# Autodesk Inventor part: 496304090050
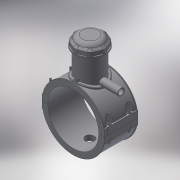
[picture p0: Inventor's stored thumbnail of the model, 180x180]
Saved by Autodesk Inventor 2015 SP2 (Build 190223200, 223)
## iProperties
Created: 2017-07
Part Number: 496304090050
Material: Generic
Description: PLASSON TAPPING SADDLE 90x50
Document SubType Name: Modeling
Designer: KIM
Mass: 716.955 g
Surface Area: 1792.48 cm^2
Volume: 716.955 cm^3
Density: 1 g/cm^3
Appearance: Default
Author: KIM
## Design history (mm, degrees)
derived "496304.ipt"
feature "Solid1::496304.ipt"
feature "Solid2::496304.ipt"
feature "Solid4::496304.ipt"
feature "Solid5::496304.ipt"
tag "TaggingFeature1"
body "Solid1"
body "Solid2"
other parameters: "d2" = 126, "d3" = 22.5, "d4" = 118, "d5" = 0, "d6" = 0.1, "d8" = 0, "d19" = 6, "d20" = 6, "d21" = 70.8, "d23" = 0, "d24" = 35.4, "d26" = 0, "d29" = 3, "d31" = 6, "d32" = 0, "d33" = 0, "d34" = 0.6, "d40" = 58.032, "d41" = 63, "d43" = 0, "d45" = 0, "d47" = 126.6, "d70" = 15, "d72" = 0, "d73" = 6, "d75" = 5, "d76" = 0, "d77" = 4.5, "d78" = 75, "d79" = 15, "d80" = 47.2, "d82" = 5 deg, "d84" = 4, "d85" = 14, "d86" = 0, "d87" = 3, "d88" = 0, "d89" = 1, "d90" = 1, "d91" = 94.4, "d92" = 0, "d93" = 0.5, "d94" = 47.36842, "d96" = 113.832, "d97" = 2.36, "d98" = 0, "d102" = 0.9, "d120" = 140 deg, "d121" = 24.228, "d122" = 20 deg, "d123" = 223.2, "d124" = 66.96, "d126" = 0, "d143" = 92.7, "d145" = 16.61538, "d149" = 1.35, "d150" = 18.27692, "d153" = 118, "d154" = 0, "d156" = 55.8, "d157" = 160 deg, "d159" = 4.32, "d161" = 1.35, "d162" = 70.8, "d163" = 0, "d164" = 45, "d167" = 9, "d168" = 54.43902, "d170" = 3.375, "d172" = 0, "d173" = 1, "d175" = 45, "d176" = 20 deg, "d177" = 6.3, "d178" = 21.6, "d180" = 0, "d183" = 8.64, "d184" = 5.04, "d185" = 38.35, "d186" = 38.35, "d187" = 55.8, "d188" = 6.48, "d189" = 6.3, "d190" = 0, "d191" = 83.7, "d193" = 6.3, "d194" = 4.13, "d195" = 90 deg, "d197" = 0, "d199" = 0, "d200" = 10.8, "d202" = 0, "d203" = 177, "d204" = 59.85, "d205" = 44.1, "d206" = 53.55, "d207" = 132.75, "d208" = 138.06, "d209" = 164.61, "d210" = 54.18, "d211" = 63, "d212" = 50.4, "d213" = 35.1, "d216" = 0, "d217" = 9, "d218" = 9, "d219" = 1.8, "d224" = 0, "d230" = 5.4, "d233" = 6, "d236" = 63, "d237" = 35.4, "d238" = 6.02433, "d240" = 35.4, "d241" = 35.4, "d242" = 35.4, "d243" = 6, "d244" = 35.4, "d245" = 35.4, "d246" = 35.4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
